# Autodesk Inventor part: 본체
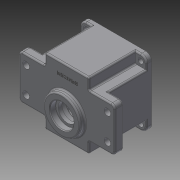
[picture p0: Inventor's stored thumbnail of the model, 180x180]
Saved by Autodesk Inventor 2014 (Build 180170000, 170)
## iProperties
Created: 2015-07
Part Number: 본체
Material: Generic
Document SubType Name: Modeling
Designer: Administrator
Density: 1 g/cm^3
Appearance: Default
Author: Administrator
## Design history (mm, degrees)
sketch "스케치1"
  geometry: L1 (-65, -30)-(65, -30); L2 (65, -30)-(65, 30); L3 (65, 30)-(-65, 30); L4 (-65, 30)-(-65, -30); L5 (-65, -30)-(65, 30); L6 (65, -30)-(-65, 30); 1 further point
  constraints: 12 end point, 2 midpoint, 2 parallel, 1 horizontal, 1 perpendicular
  dimensions: "d0" = 130 distance of L3.end L2.end; "d1" = 60 distance of L2.end L1.end
extrude "돌출1" new body sketch "스케치1" distance "d2" = 12; taper "d3" = 0 deg
sketch "스케치2"
  geometry: L1 (45, -45)-(-45, -45); L2 (-45, -45)-(-45, 45); L3 (-45, 45)-(45, 45); L4 (45, 45)-(45, -45); L5 (45, -45)-(-45, 45); L6 (-45, -45)-(45, 45); 1 further point
  constraints: 12 end point, 2 midpoint, 2 parallel, 1 horizontal, 1 perpendicular
  dimensions: "d4" = 90 distance of L2.end L3.end; "d5" = 90 distance of L1.end L2.end
extrude "돌출2" join sketch "스케치2" distance "d6" = 70; taper "d7" = 0 deg
fillet "모깎기1" dims "d8" = 5
sketch "스케치4"
  geometry: C1 r 4.5 at (-55, 17.5); C2 r 4.5 at (-55, -17.5); C3 r 4.5 at (55, 17.5); C4 r 4.5 at (55, -17.5); 1 further point
  constraints: 4 centre point, 2 vertical alignment, 1 horizontal alignment
  dimensions: "d9" = 9 diameter of C1; "d10" = 9 diameter of C2; "d11" = 9 diameter of C3; "d12" = 9 diameter of C4; "d13" = 55 horizontal distance of point (0, 0) C1.centre; "d14" = 55 horizontal distance of C3.centre point (0, 0); "d15" = 35 distance of C3.centre C4.centre; "d16" = 35 distance of C1.centre C2.centre; "d17" = 17.5 vertical distance of point (0, 0) C4.centre
extrude "돌출3" cut sketch "스케치4" distance "d18" = 70; taper "d19" = 0 deg
sketch "스케치5"
  geometry: L1 (45, 45)-(45, 30) reference; L2 (-30, -45)-(-30, -30); L3 (-30, 45)-(30, 45); L4 (30, 45)-(30, 30); L5 (30, -45)-(-30, 45); L6 (-30, -45)-(30, 45); L7 (-45, 30)-(-30, 30); L8 (30, 30)-(45, 30); L9 (45, -30)-(30, -30); L10 (-45, -30)-(-30, -30); L11 (-45, 30)-(-45, 45); L12 (-30, 45)-(-45, 45); L13 (30, 45)-(45, 45); L14 (45, 30)-(45, 45); L15 (45, -30)-(45, -45); L16 (45, -45)-(30, -45); L17 (-45, -30)-(-45, -45); L18 (-45, -45)-(-30, -45); L19 (-30, 30)-(-30, 45); L20 (30, 30)-(30, -30); L21 (30, -30)-(30, -45); L22 (-30, -30)-(-30, 30); 1 further point
  constraints: 42 end point, 10 perpendicular, 9 parallel, 3 collinear, 2 midpoint, 1 point on line
  dimensions: "d20" = 60 distance of L3.start L3.end; "d21" = 90 distance of L2.start L3.start; "d22" = 60 distance between parallel lines of L4 L2; "d23" = 90 deg angle of L21 L18
extrude "돌출4" cut sketch "스케치5" distance "d24" = 63; taper "d25" = 0 deg
fillet "모깎기2" dims "d26" = 8
sketch "스케치6"
  geometry: L1 (30, 45)-(37, 45) reference; L2 (30, 30)-(30, 45) reference; L3 (45, 30)-(30, 30) reference; L4 (45, 37)-(45, 30) reference; L5 (45, -30)-(45, -37) reference; L6 (30, -30)-(45, -30) reference; L7 (30, -45)-(30, -30) reference; L8 (37, -45)-(30, -45) reference; L9 (-30, -45)-(-37, -45) reference; L10 (-30, -30)-(-30, -45) reference; L11 (-45, -30)-(-30, -30) reference; L12 (-45, -37)-(-45, -30) reference; C1 r 3.5 at (-37, -37); C2 r 3.5 at (37, -37); C3 r 3.5 at (-37, 37); C4 r 3.5 at (37, 37); A1 r 8 centre (-37, 37) between (-37, 45) and (-45, 37) reference; A2 r 8 centre (37, 37) between (45, 37) and (37, 45) reference; A3 r 8 centre (37, -37) between (37, -45) and (45, -37) reference; A4 r 8 centre (-37, -37) between (-45, -37) and (-37, -45) reference; 1 further point
  constraints: 4 centre point, 4 coincident
  dimensions: "d27" = 7 diameter of C1; "d28" = 7 diameter of C2; "d29" = 7 diameter of C3; "d30" = 7 diameter of C4
extrude "돌출5" cut sketch "스케치6" stored distance "d31" = 63; taper "d32" = 0 deg
sketch "스케치7"
  geometry: C1 r 40 at (0, 0); 1 further point
  constraints: 1 centre point, 1 coincident
  dimensions: "d33" = 80 diameter of C1
extrude "돌출6" cut sketch "스케치7" distance "d34" = 9; taper "d35" = 0 deg
sketch "스케치9"
  geometry: C1 r 40 at (0, 0) reference; C2 r 39 at (0, 0)
  constraints: 1 centre point, 1 coincident
  dimensions: "d36" = 78 diameter of C2
extrude "돌출7" cut sketch "스케치9" distance "d37" = 52; taper "d38" = 0 deg
sketch "스케치10"
  geometry: L1 (0, 0)-(39, 0); L2 (0, 0)-(27.577, 27.577); A1 r 39 centre (0, 0) between (39, 0) and (27.577, 27.577) reference; A2 r 35 centre (0, 0) between (24.749, 24.749) and (21.762, 27.412); A3 r 4 centre (24.749, 24.749) between (21.809, 27.462) and (27.462, 21.809); A4 r 3.5 centre (19.238, 29.836) between (21.762, 27.412) and (21.809, 27.462); A5 r 3.5 centre (29.836, 19.238) between (32.777, 21.134) and (27.462, 21.809); A6 r 39 centre (0, 0) between (32.777, 21.134) and (27.577, 27.577); A7 r 3.5 centre (19.238, 29.836) between (15.988, 31.135) and (21.134, 32.777); A8 r 3.5 centre (29.836, 19.238) between (32.777, 21.134) and (31.135, 15.988); A9 r 3.5 centre (19.238, 29.836) between (21.809, 27.462) and (21.134, 32.777); A10 r 3.5 centre (29.836, 19.238) between (27.462, 21.809) and (27.412, 21.762); A11 r 39 centre (0, 0) between (27.577, 27.577) and (21.134, 32.777); A12 r 3.5 centre (29.836, 19.238) between (31.135, 15.988) and (32.777, 21.134); A13 r 3.5 centre (19.238, 29.836) between (21.134, 32.777) and (15.988, 31.135)
  constraints: 33 point on circle, 12 centre point, 4 coincident, 4 end point, 4 tangent, 1 horizontal, 1 point on line
  dimensions: "d39" = 45 deg angle of L1 L2; "d40" = 70 diameter of A2; "d41" = 8 diameter of A3; "d42" = 7 diameter of A4; "d43" = 7 diameter of A5
sketch "스케치11"
  geometry: C1 r 25 at (0, -11); 1 further point
  constraints: 1 centre point, 1 vertical alignment
  dimensions: "d44" = 50 diameter of C1; "d45" = 11 distance of point (0, 0) C1.centre
extrude "돌출8" join sketch "스케치11" distance "d46" = 7; taper "d47" = 0 deg
sketch "스케치12"
  geometry: C1 r 25 at (0, 0) reference; C2 r 16 at (0, 0); 1 further point
  constraints: 1 centre point, 1 coincident
  dimensions: "d48" = 32 diameter of C2
extrude "돌출9" cut sketch "스케치12" distance "d49" = 8; taper "d50" = 0 deg
sketch "스케치14"
  geometry: C1 r 39 at (0, 0) reference; C2 r 20.5 at (0, 11)
  constraints: 1 centre point, 1 vertical alignment
  dimensions: "d51" = 41 diameter of C2; "d52" = 11 distance of C1.centre C2.centre
extrude "돌출10" join sketch "스케치14" distance "d53" = 7; taper "d54" = 0 deg
sketch "스케치15"
  geometry: C1 r 20.5 at (0, 0) reference; C2 r 17.5 at (0, 0); 1 further point
  constraints: 1 centre point, 1 coincident
  dimensions: "d55" = 35 diameter of C2
extrude "돌출11" cut sketch "스케치15" distance "d56" = 10; taper "d57" = 0 deg
sketch "스케치16"
  geometry: C1 r 16 at (0, 0) reference; C2 r 12.5 at (0, 0); 1 further point
  constraints: 1 centre point, 1 coincident
  dimensions: "d58" = 25 diameter of C2
extrude "돌출12" cut sketch "스케치16" distance "d59" = 5; taper "d60" = 0 deg
sketch "스케치17"
  geometry: C1 r 39 at (0, 0) reference; C2 r 14 at (0, -20)
  constraints: 1 centre point, 1 vertical alignment
  dimensions: "d61" = 28 diameter of C2; "d62" = 20 distance of C2.centre C1.centre
extrude "돌출13" join sketch "스케치17" stored distance "d63" = 5; taper "d64" = 0 deg
sketch "스케치18"
  geometry: C1 r 11 at (0, -20); A1 r 14 centre (0, -20) between (-7.402, -8.117) and (7.402, -8.117) reference; 1 further point
  constraints: 1 centre point, 1 coincident
  dimensions: "d65" = 22 diameter of C1
extrude "돌출14" cut sketch "스케치18" distance "d66" = 7; taper "d67" = 0 deg
sketch "스케치19"
  geometry: C1 r 11 at (0, 0) reference; C2 r 9.5 at (0, 0); 1 further point
  constraints: 1 centre point, 1 coincident
  dimensions: "d68" = 19 diameter of C2
extrude "돌출15" cut sketch "스케치19" distance "d69" = 1; taper "d70" = 0 deg
extrude "돌출16" join sketch "스케치10" stored distance "d71" = 1; taper "d72" = 0 deg
sketch "스케치20"
  geometry: A1 r 4 centre (24.749, -24.749) between (27.462, -21.809) and (21.809, -27.462) reference; A2 r 4 centre (-24.749, -24.749) between (-21.809, -27.462) and (-27.462, -21.809) reference; A3 r 4 centre (-24.749, 24.749) between (-27.462, 21.809) and (-21.809, 27.462) reference; A4 r 4 centre (24.749, 24.749) between (21.809, 27.462) and (27.462, 21.809) reference; 4 further points
  constraints: 4 coincident
hole "구멍1" sketch "스케치20" at (-24.749, 24.749), (-24.749, -24.749), (24.749, -24.749), (24.749, 24.749) diameter "d73" = 3.459; stored, may be unused: countersink angle "d77" = 90 deg, drill point angle "d79" = 118 deg; dims "d74" = 12, "d75" = 4, "d76" = 2, "d78" = 15
sketch "스케치21"
  geometry: L1 (-30, 45)-(30, 45) reference; 2 further points
  constraints: 1 other
  dimensions: "d80" = 15 distance from line of L1 point (1.125, 30)
feature "엠보싱1" sketch "스케치21" dims "d81" = 0.5, "d82" = 0
chamfer "모따기1" distance "d83" = 1; stored, may be unused: second distance "d84" = 2, angle "d85" = 45 deg
fillet "모깎기3" dims "d86" = 3
fillet "모깎기4" dims "d87" = 2
fillet "모깎기5" dims "d88" = 2
fillet "모깎기6" dims "d89" = 2
fillet "모깎기7" dims "d90" = 2
fillet "모깎기8" dims "d91" = 0.3
chamfer "모따기2" distance "d92" = 1; stored, may be unused: second distance "d93" = 2, angle "d94" = 45 deg
fillet "모깎기9" dims "d95" = 2
fillet "모깎기10" dims "d96" = 2
fillet "모깎기11" dims "d97" = 2
fillet "모깎기12" dims "d98" = 0.3
fillet "모깎기13" dims "d99" = 2
fillet "모깎기14" dims "d100" = 3
node "솔리드1"
mirror "대칭1"
mirror "대칭2"
node "투영된 루프1"
node "투영된 루프2"
node "투영된 루프3"
node "작업 평면1"
node "작업 평면2"
node "작업 평면3"
